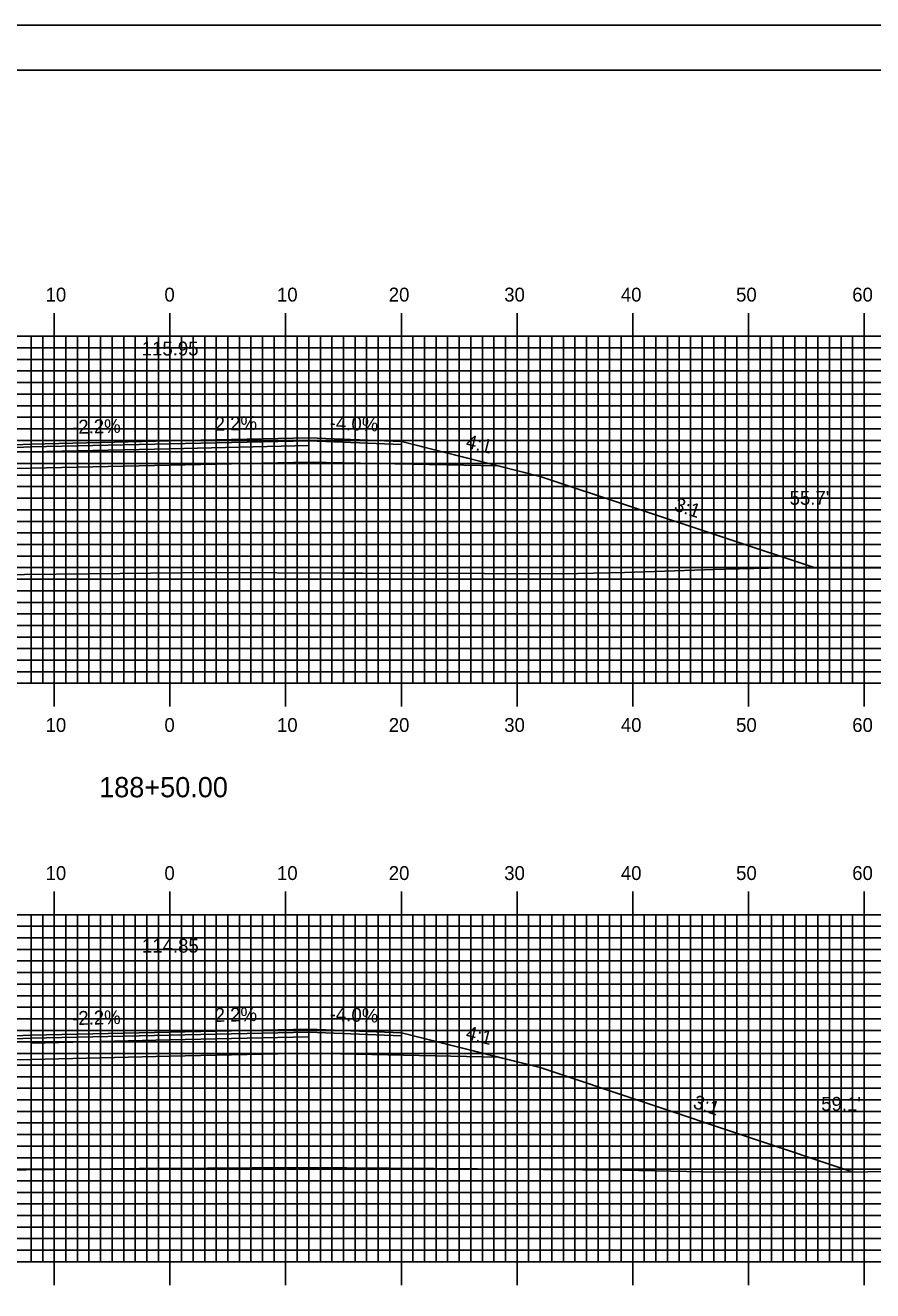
# Model space of a CAD drawing. Extents: x 1787763 to 1788106, y 442591 to 442811.
# Drawn here: x 1787916.1 to 1787989.4, y 442701.2 to 442810.5 of the extents above; entities that cross this region are included whole.
import ezdxf

# ---------------------------------------------------------------- set-up
doc = ezdxf.new("R2010")
doc.units = 0
for name, color, linetype in [('ANNOTATION', 7, 'Continuous'), ('BORDER', 7, 'Continuous'), ('D_Roadway_Centerline', 7, 'Continuous'), ('D_Roadway_Centerline_Text', 7, 'Continuous'), ('D_Roadway_Edge_Shoulder', 7, 'Continuous'), ('D_Roadway_Edge_TW', 7, 'Continuous'), ('D_Roadway_Pavement', 7, 'Continuous'), ('D_Roadway_SlopeLines', 7, 'Continuous'), ('D_Roadway_SubGrade', 7, 'Continuous'), ('D_Text_Standard', 7, 'Continuous'), ('H_V ANNOTATION', 7, 'Continuous'), ('MAJOR', 7, 'Continuous'), ('MINOR', 7, 'Continuous'), ('PLOT BOUNDARY', 7, 'Continuous'), ('S_Roadway_Centerline', 7, 'Continuous')]:
    doc.layers.add(name, color=color, linetype=linetype)

msp = doc.modelspace()

# ---------------------------------------------------------------- linework, layer by layer
at = {"layer": 'BORDER'}
msp.add_lwpolyline([(1787779.02, 442596.67), (1788099.02, 442596.67), (1788099.02, 442806.67), (1787779.02, 442806.67)], close=True, dxfattribs=at)
at = {"layer": 'D_Roadway_Centerline'}
for points in [[(1787871.78, 442762.76), (1787896.62, 442771.03), (1787900.25, 442771.94), (1787908.62, 442774.03), (1787916.62, 442774.35), (1787928.62, 442774.62), (1787940.62, 442774.88), (1787948.62, 442774.56), (1787956.98, 442772.47), (1787960.62, 442771.56), (1787984.39, 442763.64)], [(1787870.86, 442711.34), (1787896.62, 442719.93), (1787900.25, 442720.84), (1787908.62, 442722.93), (1787916.62, 442723.25), (1787928.62, 442723.51), (1787940.62, 442723.78), (1787948.62, 442723.46), (1787956.98, 442721.37), (1787960.62, 442720.46), (1787987.68, 442711.43)]]:
    msp.add_lwpolyline(points, dxfattribs=at)
at = {"layer": 'D_Roadway_Edge_Shoulder'}
for points in [[(1787916.62, 442774.35), (1787908.62, 442774.03), (1787908.62, 442773.78), (1787916.62, 442774.1)], [(1787940.62, 442774.88), (1787948.62, 442774.56), (1787948.62, 442774.31), (1787940.62, 442774.63)], [(1787916.62, 442723.25), (1787908.62, 442722.93), (1787908.62, 442722.68), (1787916.62, 442723)], [(1787940.62, 442723.78), (1787948.62, 442723.46), (1787948.62, 442723.21), (1787940.62, 442723.53)]]:
    msp.add_lwpolyline(points, close=True, dxfattribs=at)
at = {"layer": 'D_Roadway_Edge_TW'}
for points in [[(1787916.62, 442774.1), (1787916.62, 442774.35), (1787928.62, 442774.62), (1787940.62, 442774.88), (1787940.62, 442774.63), (1787928.62, 442774.37)], [(1787916.62, 442723), (1787916.62, 442723.25), (1787928.62, 442723.51), (1787940.62, 442723.78), (1787940.62, 442723.53), (1787928.62, 442723.26)]]:
    msp.add_lwpolyline(points, close=True, dxfattribs=at)
at = {"layer": 'D_Roadway_Pavement'}
for points in [[(1787916.62, 442773.69), (1787916.62, 442774.1), (1787928.62, 442774.37), (1787940.62, 442774.63), (1787940.62, 442774.22), (1787928.62, 442773.95)], [(1787916.62, 442722.58), (1787916.62, 442723), (1787928.62, 442723.26), (1787940.62, 442723.53), (1787940.62, 442723.11), (1787928.62, 442722.85)]]:
    msp.add_lwpolyline(points, close=True, dxfattribs=at)
at = {"layer": 'D_Roadway_SlopeLines'}
for points in [[(1787948.62, 442774.56), (1787960.62, 442771.56), (1787984.39, 442763.64)], [(1787948.62, 442723.46), (1787960.62, 442720.46), (1787987.68, 442711.43)]]:
    msp.add_lwpolyline(points, dxfattribs=at)
at = {"layer": 'D_Roadway_SubGrade'}
for points in [[(1787916.62, 442772.27), (1787900.25, 442771.94), (1787908.62, 442774.03), (1787908.62, 442773.78), (1787916.62, 442774.1), (1787928.62, 442774.37), (1787940.62, 442774.63), (1787948.62, 442774.31), (1787948.62, 442774.56), (1787956.98, 442772.47), (1787940.62, 442772.8), (1787928.62, 442772.54)], [(1787916.62, 442721.16), (1787900.25, 442720.84), (1787908.62, 442722.93), (1787908.62, 442722.68), (1787916.62, 442723), (1787928.62, 442723.26), (1787940.62, 442723.53), (1787948.62, 442723.21), (1787948.62, 442723.46), (1787956.98, 442721.37), (1787940.62, 442721.69), (1787928.62, 442721.43)]]:
    msp.add_lwpolyline(points, close=True, dxfattribs=at)
at = {"layer": 'MAJOR'}
for p, q in [((1787918.62, 442785.67), (1787918.62, 442783.67)), ((1787928.62, 442785.67), (1787928.62, 442783.67)), ((1787938.62, 442785.67), (1787938.62, 442783.67)), ((1787948.62, 442785.67), (1787948.62, 442783.67)), ((1787958.62, 442785.67), (1787958.62, 442783.67)), ((1787968.62, 442785.67), (1787968.62, 442783.67)), ((1787978.62, 442785.67), (1787978.62, 442783.67)), ((1787988.62, 442785.67), (1787988.62, 442783.67)), ((1787788.62, 442783.67), (1788068.62, 442783.67)), ((1787788.62, 442783.67), (1788068.62, 442783.67)), ((1787918.62, 442753.67), (1787918.62, 442783.67)), ((1787928.62, 442753.67), (1787928.62, 442783.67)), ((1787938.62, 442753.67), (1787938.62, 442783.67)), ((1787948.62, 442753.67), (1787948.62, 442783.67)), ((1787958.62, 442753.67), (1787958.62, 442783.67)), ((1787968.62, 442753.67), (1787968.62, 442783.67)), ((1787978.62, 442753.67), (1787978.62, 442783.67)), ((1787988.62, 442753.67), (1787988.62, 442783.67)), ((1787788.62, 442778.67), (1788068.62, 442778.67)), ((1787788.62, 442773.67), (1788068.62, 442773.67)), ((1787788.62, 442768.67), (1788068.62, 442768.67)), ((1787788.62, 442763.67), (1788068.62, 442763.67)), ((1787788.62, 442758.67), (1788068.62, 442758.67)), ((1787788.62, 442753.67), (1788068.62, 442753.67)), ((1787788.62, 442753.67), (1788068.62, 442753.67)), ((1787918.62, 442751.66), (1787918.62, 442753.67)), ((1787928.62, 442751.66), (1787928.62, 442753.67)), ((1787938.62, 442751.66), (1787938.62, 442753.67)), ((1787948.62, 442751.66), (1787948.62, 442753.67)), ((1787958.62, 442751.66), (1787958.62, 442753.67)), ((1787968.62, 442751.66), (1787968.62, 442753.67)), ((1787978.62, 442751.66), (1787978.62, 442753.67)), ((1787988.62, 442751.66), (1787988.62, 442753.67)), ((1787918.62, 442735.67), (1787918.62, 442733.67)), ((1787928.62, 442735.67), (1787928.62, 442733.67)), ((1787938.62, 442735.67), (1787938.62, 442733.67)), ((1787948.62, 442735.67), (1787948.62, 442733.67)), ((1787958.62, 442735.67), (1787958.62, 442733.67)), ((1787968.62, 442735.67), (1787968.62, 442733.67)), ((1787978.62, 442735.67), (1787978.62, 442733.67)), ((1787988.62, 442735.67), (1787988.62, 442733.67)), ((1787788.62, 442733.67), (1788068.62, 442733.67)), ((1787788.62, 442733.67), (1788068.62, 442733.67)), ((1787918.62, 442703.67), (1787918.62, 442733.67)), ((1787928.62, 442703.67), (1787928.62, 442733.67)), ((1787938.62, 442703.67), (1787938.62, 442733.67)), ((1787948.62, 442703.67), (1787948.62, 442733.67)), ((1787958.62, 442703.67), (1787958.62, 442733.67)), ((1787968.62, 442703.67), (1787968.62, 442733.67)), ((1787978.62, 442703.67), (1787978.62, 442733.67)), ((1787988.62, 442703.67), (1787988.62, 442733.67)), ((1787788.62, 442728.67), (1788068.62, 442728.67)), ((1787788.62, 442723.67), (1788068.62, 442723.67)), ((1787788.62, 442718.67), (1788068.62, 442718.67)), ((1787788.62, 442713.67), (1788068.62, 442713.67)), ((1787788.62, 442708.67), (1788068.62, 442708.67)), ((1787788.62, 442703.67), (1788068.62, 442703.67)), ((1787788.62, 442703.67), (1788068.62, 442703.67)), ((1787918.62, 442701.66), (1787918.62, 442703.67)), ((1787928.62, 442701.66), (1787928.62, 442703.67)), ((1787938.62, 442701.66), (1787938.62, 442703.67)), ((1787948.62, 442701.66), (1787948.62, 442703.67)), ((1787958.62, 442701.66), (1787958.62, 442703.67)), ((1787968.62, 442701.66), (1787968.62, 442703.67)), ((1787978.62, 442701.66), (1787978.62, 442703.67)), ((1787988.62, 442701.66), (1787988.62, 442703.67))]:
    msp.add_line(p, q, dxfattribs=at)
at = {"layer": 'MINOR'}
for p, q in [((1787916.62, 442753.67), (1787916.62, 442783.67)), ((1787917.62, 442753.67), (1787917.62, 442783.67)), ((1787919.62, 442753.67), (1787919.62, 442783.67)), ((1787920.62, 442753.67), (1787920.62, 442783.67)), ((1787921.62, 442753.67), (1787921.62, 442783.67)), ((1787922.62, 442753.67), (1787922.62, 442783.67)), ((1787923.62, 442753.67), (1787923.62, 442783.67)), ((1787924.62, 442753.67), (1787924.62, 442783.67)), ((1787925.62, 442753.67), (1787925.62, 442783.67)), ((1787926.62, 442753.67), (1787926.62, 442783.67)), ((1787927.62, 442753.67), (1787927.62, 442783.67)), ((1787929.62, 442753.67), (1787929.62, 442783.67)), ((1787930.62, 442753.67), (1787930.62, 442783.67)), ((1787931.62, 442753.67), (1787931.62, 442783.67)), ((1787932.62, 442753.67), (1787932.62, 442783.67)), ((1787933.62, 442753.67), (1787933.62, 442783.67)), ((1787934.62, 442753.67), (1787934.62, 442783.67)), ((1787935.62, 442753.67), (1787935.62, 442783.67)), ((1787936.62, 442753.67), (1787936.62, 442783.67)), ((1787937.62, 442753.67), (1787937.62, 442783.67)), ((1787939.62, 442753.67), (1787939.62, 442783.67)), ((1787940.62, 442753.67), (1787940.62, 442783.67)), ((1787941.62, 442753.67), (1787941.62, 442783.67)), ((1787942.62, 442753.67), (1787942.62, 442783.67)), ((1787943.62, 442753.67), (1787943.62, 442783.67)), ((1787944.62, 442753.67), (1787944.62, 442783.67)), ((1787945.62, 442753.67), (1787945.62, 442783.67)), ((1787946.62, 442753.67), (1787946.62, 442783.67)), ((1787947.62, 442753.67), (1787947.62, 442783.67)), ((1787949.62, 442753.67), (1787949.62, 442783.67)), ((1787950.62, 442753.67), (1787950.62, 442783.67)), ((1787951.62, 442753.67), (1787951.62, 442783.67)), ((1787952.62, 442753.67), (1787952.62, 442783.67)), ((1787953.62, 442753.67), (1787953.62, 442783.67)), ((1787954.62, 442753.67), (1787954.62, 442783.67)), ((1787955.62, 442753.67), (1787955.62, 442783.67)), ((1787956.62, 442753.67), (1787956.62, 442783.67)), ((1787957.62, 442753.67), (1787957.62, 442783.67)), ((1787959.62, 442753.67), (1787959.62, 442783.67)), ((1787960.62, 442753.67), (1787960.62, 442783.67)), ((1787961.62, 442753.67), (1787961.62, 442783.67)), ((1787962.62, 442753.67), (1787962.62, 442783.67)), ((1787963.62, 442753.67), (1787963.62, 442783.67)), ((1787964.62, 442753.67), (1787964.62, 442783.67)), ((1787965.62, 442753.67), (1787965.62, 442783.67)), ((1787966.62, 442753.67), (1787966.62, 442783.67)), ((1787967.62, 442753.67), (1787967.62, 442783.67)), ((1787969.62, 442753.67), (1787969.62, 442783.67)), ((1787970.62, 442753.67), (1787970.62, 442783.67)), ((1787971.62, 442753.67), (1787971.62, 442783.67)), ((1787972.62, 442753.67), (1787972.62, 442783.67)), ((1787973.62, 442753.67), (1787973.62, 442783.67)), ((1787974.62, 442753.67), (1787974.62, 442783.67)), ((1787975.62, 442753.67), (1787975.62, 442783.67)), ((1787976.62, 442753.67), (1787976.62, 442783.67)), ((1787977.62, 442753.67), (1787977.62, 442783.67)), ((1787979.62, 442753.67), (1787979.62, 442783.67)), ((1787980.62, 442753.67), (1787980.62, 442783.67)), ((1787981.62, 442753.67), (1787981.62, 442783.67)), ((1787982.62, 442753.67), (1787982.62, 442783.67)), ((1787983.62, 442753.67), (1787983.62, 442783.67)), ((1787984.62, 442753.67), (1787984.62, 442783.67)), ((1787985.62, 442753.67), (1787985.62, 442783.67)), ((1787986.62, 442753.67), (1787986.62, 442783.67)), ((1787987.62, 442753.67), (1787987.62, 442783.67)), ((1787788.62, 442782.67), (1788068.62, 442782.67)), ((1787788.62, 442781.67), (1788068.62, 442781.67)), ((1787788.62, 442780.67), (1788068.62, 442780.67)), ((1787788.62, 442779.67), (1788068.62, 442779.67)), ((1787788.62, 442777.67), (1788068.62, 442777.67)), ((1787788.62, 442776.67), (1788068.62, 442776.67)), ((1787788.62, 442775.67), (1788068.62, 442775.67)), ((1787788.62, 442774.67), (1788068.62, 442774.67)), ((1787788.62, 442772.67), (1788068.62, 442772.67)), ((1787788.62, 442771.67), (1788068.62, 442771.67)), ((1787788.62, 442770.67), (1788068.62, 442770.67)), ((1787788.62, 442769.67), (1788068.62, 442769.67)), ((1787788.62, 442767.67), (1788068.62, 442767.67)), ((1787788.62, 442766.67), (1788068.62, 442766.67)), ((1787788.62, 442765.67), (1788068.62, 442765.67)), ((1787788.62, 442764.67), (1788068.62, 442764.67)), ((1787788.62, 442762.67), (1788068.62, 442762.67)), ((1787788.62, 442761.67), (1788068.62, 442761.67)), ((1787788.62, 442760.67), (1788068.62, 442760.67)), ((1787788.62, 442759.67), (1788068.62, 442759.67)), ((1787788.62, 442757.67), (1788068.62, 442757.67)), ((1787788.62, 442756.67), (1788068.62, 442756.67)), ((1787788.62, 442755.67), (1788068.62, 442755.67)), ((1787788.62, 442754.67), (1788068.62, 442754.67)), ((1787916.62, 442703.67), (1787916.62, 442733.67)), ((1787917.62, 442703.67), (1787917.62, 442733.67)), ((1787919.62, 442703.67), (1787919.62, 442733.67)), ((1787920.62, 442703.67), (1787920.62, 442733.67)), ((1787921.62, 442703.67), (1787921.62, 442733.67)), ((1787922.62, 442703.67), (1787922.62, 442733.67)), ((1787923.62, 442703.67), (1787923.62, 442733.67)), ((1787924.62, 442703.67), (1787924.62, 442733.67)), ((1787925.62, 442703.67), (1787925.62, 442733.67)), ((1787926.62, 442703.67), (1787926.62, 442733.67)), ((1787927.62, 442703.67), (1787927.62, 442733.67)), ((1787929.62, 442703.67), (1787929.62, 442733.67)), ((1787930.62, 442703.67), (1787930.62, 442733.67)), ((1787931.62, 442703.67), (1787931.62, 442733.67)), ((1787932.62, 442703.67), (1787932.62, 442733.67)), ((1787933.62, 442703.67), (1787933.62, 442733.67)), ((1787934.62, 442703.67), (1787934.62, 442733.67)), ((1787935.62, 442703.67), (1787935.62, 442733.67)), ((1787936.62, 442703.67), (1787936.62, 442733.67)), ((1787937.62, 442703.67), (1787937.62, 442733.67)), ((1787939.62, 442703.67), (1787939.62, 442733.67)), ((1787940.62, 442703.67), (1787940.62, 442733.67)), ((1787941.62, 442703.67), (1787941.62, 442733.67)), ((1787942.62, 442703.67), (1787942.62, 442733.67)), ((1787943.62, 442703.67), (1787943.62, 442733.67)), ((1787944.62, 442703.67), (1787944.62, 442733.67)), ((1787945.62, 442703.67), (1787945.62, 442733.67)), ((1787946.62, 442703.67), (1787946.62, 442733.67)), ((1787947.62, 442703.67), (1787947.62, 442733.67)), ((1787949.62, 442703.67), (1787949.62, 442733.67)), ((1787950.62, 442703.67), (1787950.62, 442733.67)), ((1787951.62, 442703.67), (1787951.62, 442733.67)), ((1787952.62, 442703.67), (1787952.62, 442733.67)), ((1787953.62, 442703.67), (1787953.62, 442733.67)), ((1787954.62, 442703.67), (1787954.62, 442733.67)), ((1787955.62, 442703.67), (1787955.62, 442733.67)), ((1787956.62, 442703.67), (1787956.62, 442733.67)), ((1787957.62, 442703.67), (1787957.62, 442733.67)), ((1787959.62, 442703.67), (1787959.62, 442733.67)), ((1787960.62, 442703.67), (1787960.62, 442733.67)), ((1787961.62, 442703.67), (1787961.62, 442733.67)), ((1787962.62, 442703.67), (1787962.62, 442733.67)), ((1787963.62, 442703.67), (1787963.62, 442733.67)), ((1787964.62, 442703.67), (1787964.62, 442733.67)), ((1787965.62, 442703.67), (1787965.62, 442733.67)), ((1787966.62, 442703.67), (1787966.62, 442733.67)), ((1787967.62, 442703.67), (1787967.62, 442733.67)), ((1787969.62, 442703.67), (1787969.62, 442733.67)), ((1787970.62, 442703.67), (1787970.62, 442733.67)), ((1787971.62, 442703.67), (1787971.62, 442733.67)), ((1787972.62, 442703.67), (1787972.62, 442733.67)), ((1787973.62, 442703.67), (1787973.62, 442733.67)), ((1787974.62, 442703.67), (1787974.62, 442733.67)), ((1787975.62, 442703.67), (1787975.62, 442733.67)), ((1787976.62, 442703.67), (1787976.62, 442733.67)), ((1787977.62, 442703.67), (1787977.62, 442733.67)), ((1787979.62, 442703.67), (1787979.62, 442733.67)), ((1787980.62, 442703.67), (1787980.62, 442733.67)), ((1787981.62, 442703.67), (1787981.62, 442733.67)), ((1787982.62, 442703.67), (1787982.62, 442733.67)), ((1787983.62, 442703.67), (1787983.62, 442733.67)), ((1787984.62, 442703.67), (1787984.62, 442733.67)), ((1787985.62, 442703.67), (1787985.62, 442733.67)), ((1787986.62, 442703.67), (1787986.62, 442733.67)), ((1787987.62, 442703.67), (1787987.62, 442733.67)), ((1787788.62, 442732.67), (1788068.62, 442732.67)), ((1787788.62, 442731.67), (1788068.62, 442731.67)), ((1787788.62, 442730.67), (1788068.62, 442730.67)), ((1787788.62, 442729.67), (1788068.62, 442729.67)), ((1787788.62, 442727.67), (1788068.62, 442727.67)), ((1787788.62, 442726.67), (1788068.62, 442726.67)), ((1787788.62, 442725.67), (1788068.62, 442725.67)), ((1787788.62, 442724.67), (1788068.62, 442724.67)), ((1787788.62, 442722.67), (1788068.62, 442722.67)), ((1787788.62, 442721.67), (1788068.62, 442721.67)), ((1787788.62, 442720.67), (1788068.62, 442720.67)), ((1787788.62, 442719.67), (1788068.62, 442719.67)), ((1787788.62, 442717.67), (1788068.62, 442717.67)), ((1787788.62, 442716.67), (1788068.62, 442716.67)), ((1787788.62, 442715.67), (1788068.62, 442715.67)), ((1787788.62, 442714.67), (1788068.62, 442714.67)), ((1787788.62, 442712.67), (1788068.62, 442712.67)), ((1787788.62, 442711.67), (1788068.62, 442711.67)), ((1787788.62, 442710.67), (1788068.62, 442710.67)), ((1787788.62, 442709.67), (1788068.62, 442709.67)), ((1787788.62, 442707.67), (1788068.62, 442707.67)), ((1787788.62, 442706.67), (1788068.62, 442706.67)), ((1787788.62, 442705.67), (1788068.62, 442705.67)), ((1787788.62, 442704.67), (1788068.62, 442704.67))]:
    msp.add_line(p, q, dxfattribs=at)
at = {"layer": 'PLOT BOUNDARY'}
msp.add_lwpolyline([(1787762.83, 442590.55), (1788102.83, 442590.55), (1788102.83, 442810.55), (1787762.83, 442810.55)], close=True, dxfattribs=at)
at = {"layer": 'S_Roadway_Centerline'}
for points in [[(1787860.53, 442762.53), (1787866.88, 442762.69), (1787872.49, 442762.77), (1787881.63, 442762.9), (1787886.22, 442762.95), (1787893.24, 442762.94), (1787905.25, 442763), (1787908.26, 442762.98), (1787913.29, 442763.06), (1787924.29, 442763.15), (1787932.21, 442763.26), (1787943.5, 442763.2), (1787945.27, 442763.18), (1787955.82, 442763.16), (1787962.52, 442763.13), (1787967.92, 442763.25), (1787976.54, 442763.53), (1787981.61, 442763.64), (1787991.77, 442763.65)], [(1787860.39, 442711.13), (1787863.81, 442711.2), (1787878.04, 442711.49), (1787894.44, 442711.58), (1787896.98, 442711.59), (1787908.11, 442711.56), (1787916.2, 442711.63), (1787925.96, 442711.73), (1787931.85, 442711.76), (1787935.76, 442711.79), (1787943.88, 442711.79), (1787955.19, 442711.7), (1787957.42, 442711.68), (1787967.75, 442711.6), (1787974.69, 442711.45), (1787980.13, 442711.43), (1787988.93, 442711.44), (1787993.21, 442711.48)]]:
    msp.add_lwpolyline(points, dxfattribs=at)

# ---------------------------------------------------------------- texts
at = {"layer": 'ANNOTATION'}
for s, rotation, p in [('-2.2%', 1.2603, (1787920.18, 442775.23)), ('2.2%', 1.2603, (1787932.5, 442775.5)), ('-4.0%', 357.7094, (1787942.41, 442775.61)), ('4:1', 345.9638, (1787954.12, 442774.05)), ('3:1', 341.5652, (1787972.11, 442768.64)), ('-2.2%', 1.2603, (1787920.18, 442724.13)), ('2.2%', 1.2603, (1787932.5, 442724.4)), ('-4.0%', 357.7094, (1787942.41, 442724.51)), ('4:1', 345.9638, (1787954.12, 442722.94)), ('3:1', 341.5652, (1787973.75, 442716.99))]:
    msp.add_text(s, height=1.2, rotation=rotation, dxfattribs=at).set_placement(p)
at = {"layer": 'D_Roadway_Centerline'}
for s, p in [('C', (1787928.61, 442774.62)), ('L', (1787928.62, 442774.61)), ('C', (1787928.61, 442723.51)), ('L', (1787928.62, 442723.5))]:
    msp.add_text(s, height=0.0146, dxfattribs=at).set_placement(p)
at = {"layer": 'D_Roadway_Centerline_Text'}
for s, p in [('115.95', (1787926.18, 442782.01)), ('114.85', (1787926.2, 442730.39))]:
    msp.add_text(s, height=1.2, dxfattribs=at).set_placement(p)
at = {"layer": 'D_Text_Standard'}
for s, p in [("55.7'", (1787982.18, 442769.1)), ("59.1'", (1787984.91, 442716.72))]:
    msp.add_text(s, height=1.2, dxfattribs=at).set_placement(p)
at = {"layer": 'H_V ANNOTATION'}
for s, height, p in [('10', 1.2, (1787917.87, 442786.67)), ('0', 1.2, (1787928.14, 442786.67)), ('10', 1.2, (1787937.87, 442786.67)), ('20', 1.2, (1787947.53, 442786.67)), ('30', 1.2, (1787957.51, 442786.67)), ('40', 1.2, (1787967.59, 442786.67)), ('50', 1.2, (1787977.55, 442786.67)), ('60', 1.2, (1787987.59, 442786.67)), ('10', 1.2, (1787917.87, 442749.47)), ('0', 1.2, (1787928.14, 442749.47)), ('10', 1.2, (1787937.87, 442749.47)), ('20', 1.2, (1787947.53, 442749.47)), ('30', 1.2, (1787957.51, 442749.47)), ('40', 1.2, (1787967.59, 442749.47)), ('50', 1.2, (1787977.55, 442749.47)), ('60', 1.2, (1787987.59, 442749.47)), ('188+50.00', 1.75, (1787922.5, 442743.82)), ('10', 1.2, (1787917.87, 442736.67)), ('0', 1.2, (1787928.14, 442736.67)), ('10', 1.2, (1787937.87, 442736.67)), ('20', 1.2, (1787947.53, 442736.67)), ('30', 1.2, (1787957.51, 442736.67)), ('40', 1.2, (1787967.59, 442736.67)), ('50', 1.2, (1787977.55, 442736.67)), ('60', 1.2, (1787987.59, 442736.67))]:
    msp.add_text(s, height=height, dxfattribs=at).set_placement(p)

doc.saveas('drawing.dxf')
